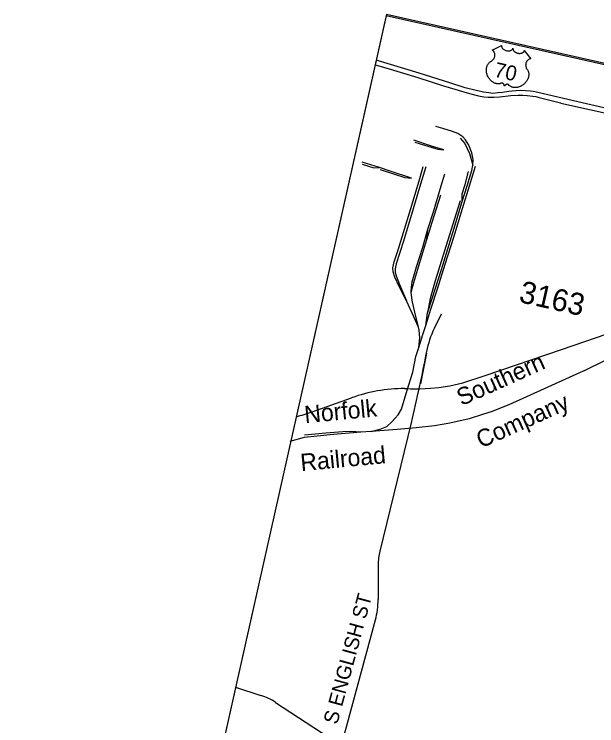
# Model space of a CAD drawing. Extents: x 1784499 to 1786147, y 841097 to 842538.
# Drawn here: x 1784498.9 to 1784675.3, y 842322.5 to 842538 of the extents above; entities that cross this region are included whole.
import ezdxf

# ---------------------------------------------------------------- set-up
doc = ezdxf.new("R2010")
doc.units = 0
for name, color, linetype in [('Exist Railroad Mainline', 7, 'Continuous'), ('Exist Railroad Mainline Label', 7, 'Continuous'), ('Exist Railroad Siding', 7, 'Continuous'), ('Exist Road Primary US Divided Attributed', 7, 'Continuous'), ('Exist Road Primary US Shield CELL', 7, 'Continuous'), ('Exist Road Primary US Shield Number Label', 7, 'Continuous'), ('Exist Road Secondary Type 51 Attributed', 7, 'Continuous'), ('Exist Road Secondary Type 51 Number Label', 7, 'Continuous'), ('Old_Level_40', 7, 'Continuous'), ('Prop DSN Text', 7, 'Continuous'), ('Scratch_Level_3', 7, 'Continuous')]:
    doc.layers.add(name, color=color, linetype=linetype)

msp = doc.modelspace()

# ---------------------------------------------------------------- linework, layer by layer
at = {"layer": 'Exist Railroad Mainline'}
msp.add_line((1784607.02, 842411.57), (1784603.83, 842411.38), dxfattribs=at)
for points in [[(1784691.01, 842439.02), (1784685.09, 842436.5), (1784677.01, 842432.69), (1784672.29, 842430.37), (1784671.48, 842430.01)], [(1784672.29, 842430.37), (1784648.63, 842419.69), (1784643.34, 842417.61), (1784641.02, 842416.82), (1784636.61, 842415.42)], [(1784636.61, 842415.42), (1784630.85, 842414.14), (1784626.2, 842413.36), (1784620.58, 842412.7), (1784614.83, 842412.18), (1784607.02, 842411.57)], [(1784603.83, 842411.38), (1784595.59, 842410.67), (1784586.73, 842409.78), (1784582.4, 842408.54)]]:
    msp.add_lwpolyline(points, dxfattribs=at)
at = {"layer": 'Exist Railroad Siding'}
for p, q in [((1784609.48, 842491.52), (1784604.3, 842493.15)), ((1784623.89, 842469.79), (1784624.18, 842472.9)), ((1784623.54, 842443.74), (1784624.03, 842447.53))]:
    msp.add_line(p, q, dxfattribs=at)
for points in [[(1784637.76, 842492.23), (1784637.87, 842493.96), (1784637.45, 842496.05), (1784636.51, 842498.36), (1784635.59, 842499.91), (1784634.7, 842500.82), (1784633.85, 842501.44), (1784633.19, 842501.88), (1784631.65, 842502.42), (1784628.73, 842503.34), (1784626.55, 842503.98)], [(1784628.98, 842496.93), (1784625.3, 842498.07), (1784619.9, 842499.79)], [(1784620.2, 842499.24), (1784624.1, 842498.02), (1784627.16, 842497.07), (1784628.98, 842496.93)], [(1784633.94, 842500.42), (1784635.3, 842498.87), (1784636.78, 842495.83), (1784637.76, 842492.23)], [(1784604.26, 842492.59), (1784607.76, 842491.49), (1784609.48, 842491.52)], [(1784634.51, 842481.24), (1784636.08, 842485.97), (1784637.44, 842490.65), (1784637.76, 842492.23)], [(1784619.15, 842488.35), (1784612.69, 842490.41), (1784609.48, 842491.52)], [(1784609.68, 842490.91), (1784613.7, 842489.65), (1784617.19, 842488.51), (1784619.15, 842488.35)], [(1784617.66, 842451.23), (1784615.43, 842455.54), (1784614.17, 842458.35), (1784613.6, 842459.95), (1784613.51, 842461.21), (1784613.95, 842462.96), (1784615.25, 842466.93), (1784617.06, 842472.93), (1784619.42, 842480.5), (1784621.73, 842488.23), (1784622.76, 842491.84)], [(1784623.49, 842491.72), (1784621.96, 842486.52), (1784619.66, 842479.02), (1784616.73, 842469.25), (1784614.59, 842462.43), (1784614.23, 842460.85), (1784614.2, 842459.9), (1784614.52, 842458.79), (1784615.6, 842456.12), (1784617.66, 842451.23)], [(1784623.54, 842443.74), (1784625.1, 842448.7), (1784627.02, 842454.77), (1784629.37, 842462.24), (1784631.98, 842470.48), (1784634.65, 842479.17), (1784636.75, 842486), (1784638.59, 842491.94)], [(1784634.51, 842481.24), (1784634.53, 842483.57), (1784635.47, 842486.44), (1784636.45, 842490.3)], [(1784624.18, 842472.9), (1784625.82, 842478.17), (1784628.16, 842486.04), (1784629.29, 842489.67)], [(1784623.89, 842469.79), (1784625.48, 842475.02), (1784628.04, 842483.26)], [(1784633.9, 842481.48), (1784632.13, 842475.68), (1784629.22, 842466.32), (1784626.4, 842457.23), (1784624.89, 842451.88), (1784624.03, 842447.53)], [(1784624.03, 842447.53), (1784625.49, 842451.84), (1784628.25, 842460.7), (1784631.68, 842471.87), (1784634.51, 842481.24)], [(1784619.12, 842453.83), (1784619.17, 842455.29), (1784619.36, 842456.92), (1784620.68, 842461.45), (1784622.58, 842467.43), (1784624.18, 842472.9)], [(1784619.12, 842453.83), (1784620.09, 842457.41), (1784622.32, 842464.82), (1784623.89, 842469.79)], [(1784621.27, 842443.18), (1784620.22, 842447.7), (1784619.43, 842451.24), (1784619.12, 842453.83)], [(1784621.27, 842443.18), (1784619.91, 842446.34), (1784617.75, 842450.96), (1784617.66, 842451.23)], [(1784621.46, 842437), (1784621.77, 842440.02), (1784621.54, 842442.3), (1784621.27, 842443.18)], [(1784621.46, 842437), (1784622.65, 842440.95), (1784623.54, 842443.74)], [(1784607.02, 842411.57), (1784609.68, 842412.32), (1784611.7, 842413.17), (1784613.24, 842414.52), (1784614.3, 842415.67), (1784615.2, 842416.67), (1784616.15, 842418.34), (1784617.91, 842424.08), (1784619.65, 842429.61), (1784620.55, 842434.31), (1784621.46, 842437)], [(1784603.83, 842411.38), (1784600.9, 842411.63), (1784598.45, 842411.52), (1784593.26, 842411.06), (1784586.82, 842410.5)]]:
    msp.add_lwpolyline(points, dxfattribs=at)
at = {"layer": 'Exist Road Primary US Divided Attributed'}
for points in [[(1784608.16, 842522.67), (1784611.39, 842521.75), (1784621.15, 842518.78), (1784628.84, 842516.34), (1784636.81, 842514), (1784639.45, 842513.24), (1784641.15, 842512.92), (1784642.37, 842512.84), (1784644.13, 842512.86), (1784645.93, 842512.95), (1784649.28, 842513.33), (1784651.55, 842513.49), (1784652.91, 842513.46), (1784654.24, 842513.4), (1784655.91, 842513.18), (1784656.81, 842513.03), (1784657.86, 842512.77), (1784664.37, 842511.11), (1784664.46, 842511.09), (1784673.09, 842509.12), (1784678.18, 842508.03)], [(1784685.73, 842507.7), (1784669.58, 842511.47), (1784657.44, 842514.28), (1784656.05, 842514.55), (1784655.12, 842514.68), (1784653.76, 842514.82), (1784652.09, 842514.83), (1784649.69, 842514.68), (1784648.71, 842514.58), (1784646.73, 842514.27), (1784645.3, 842514.14), (1784643.81, 842514.01), (1784642.65, 842514.13), (1784641.85, 842514.26), (1784641.03, 842514.38), (1784638.77, 842514.89), (1784635.46, 842515.72), (1784630.81, 842517.21), (1784621.54, 842520.1), (1784608.47, 842524.06)]]:
    msp.add_lwpolyline(points, dxfattribs=at)
at = {"layer": 'Exist Road Primary US Shield CELL'}
for p, q in [((1784646.49, 842528.48), (1784646.48, 842528.38)), ((1784649.89, 842527.59), (1784649.93, 842527.72)), ((1784649.93, 842527.72), (1784649.91, 842527.61)), ((1784653.34, 842526.88), (1784653.36, 842526.95))]:
    msp.add_line(p, q, dxfattribs=at)
at = {"layer": 'Exist Road Primary US Shield Number Label'}
for p, q in [((1784643.66, 842527.11), (1784646.49, 842528.48)), ((1784643.73, 842527.06), (1784643.66, 842527.11)), ((1784643.83, 842526.98), (1784643.73, 842527.06)), ((1784643.94, 842526.88), (1784643.83, 842526.98)), ((1784644.02, 842526.79), (1784643.94, 842526.88)), ((1784644.11, 842526.68), (1784644.02, 842526.79)), ((1784644.19, 842526.55), (1784644.11, 842526.68)), ((1784644.27, 842526.41), (1784644.19, 842526.55)), ((1784646.48, 842528.38), (1784646.47, 842528.26)), ((1784646.47, 842528.26), (1784646.48, 842528.19)), ((1784646.48, 842528.19), (1784646.51, 842528.07)), ((1784646.51, 842528.07), (1784646.57, 842527.91)), ((1784646.57, 842527.91), (1784646.66, 842527.75)), ((1784646.66, 842527.75), (1784646.78, 842527.6)), ((1784646.78, 842527.6), (1784646.86, 842527.51)), ((1784646.86, 842527.51), (1784647.01, 842527.39)), ((1784647.01, 842527.39), (1784647.17, 842527.27)), ((1784647.17, 842527.27), (1784647.37, 842527.16)), ((1784647.37, 842527.16), (1784647.57, 842527.07)), ((1784647.57, 842527.07), (1784647.8, 842526.99)), ((1784647.8, 842526.99), (1784648.02, 842526.94)), ((1784648.02, 842526.94), (1784648.27, 842526.9)), ((1784648.27, 842526.9), (1784648.56, 842526.89)), ((1784648.56, 842526.89), (1784648.69, 842526.9)), ((1784648.69, 842526.9), (1784648.84, 842526.91)), ((1784648.84, 842526.91), (1784648.98, 842526.94)), ((1784648.98, 842526.94), (1784649.14, 842526.98)), ((1784649.14, 842526.98), (1784649.28, 842527.03)), ((1784649.28, 842527.03), (1784649.38, 842527.08)), ((1784649.38, 842527.08), (1784649.54, 842527.17)), ((1784649.54, 842527.17), (1784649.67, 842527.27)), ((1784649.67, 842527.27), (1784649.72, 842527.33)), ((1784649.72, 842527.33), (1784649.78, 842527.39)), ((1784649.78, 842527.39), (1784649.86, 842527.53)), ((1784649.86, 842527.53), (1784649.89, 842527.59)), ((1784649.91, 842527.61), (1784649.91, 842527.53)), ((1784649.91, 842527.53), (1784649.91, 842527.46)), ((1784649.91, 842527.46), (1784649.92, 842527.38)), ((1784649.92, 842527.38), (1784649.95, 842527.27)), ((1784649.95, 842527.27), (1784649.99, 842527.17)), ((1784649.99, 842527.17), (1784650.07, 842527.02)), ((1784650.07, 842527.02), (1784650.12, 842526.94)), ((1784650.12, 842526.94), (1784650.17, 842526.88)), ((1784650.17, 842526.88), (1784650.31, 842526.73)), ((1784650.31, 842526.73), (1784650.47, 842526.59)), ((1784650.47, 842526.59), (1784650.56, 842526.53)), ((1784650.56, 842526.53), (1784650.65, 842526.47)), ((1784653.07, 842526.48), (1784653.15, 842526.55)), ((1784653.15, 842526.55), (1784653.21, 842526.63)), ((1784653.21, 842526.63), (1784653.27, 842526.71)), ((1784653.27, 842526.71), (1784653.31, 842526.8)), ((1784653.31, 842526.8), (1784653.34, 842526.88)), ((1784653.36, 842526.95), (1784655.33, 842524.5)), ((1784643.93, 842524.22), (1784644.03, 842524.34)), ((1784644.03, 842524.34), (1784644.1, 842524.44)), ((1784644.1, 842524.44), (1784644.19, 842524.59)), ((1784644.19, 842524.59), (1784644.25, 842524.69)), ((1784644.25, 842524.69), (1784644.31, 842524.83)), ((1784644.34, 842526.24), (1784644.27, 842526.41)), ((1784644.31, 842524.83), (1784644.36, 842524.97)), ((1784644.39, 842526.06), (1784644.34, 842526.24)), ((1784644.36, 842524.97), (1784644.4, 842525.14)), ((1784644.42, 842525.94), (1784644.39, 842526.06)), ((1784644.4, 842525.14), (1784644.43, 842525.28)), ((1784644.45, 842525.76), (1784644.42, 842525.94)), ((1784644.43, 842525.28), (1784644.45, 842525.45)), ((1784644.45, 842525.62), (1784644.45, 842525.76)), ((1784644.45, 842525.45), (1784644.45, 842525.62)), ((1784650.65, 842526.47), (1784650.76, 842526.41)), ((1784650.76, 842526.41), (1784650.88, 842526.35)), ((1784650.88, 842526.35), (1784651, 842526.3)), ((1784651, 842526.3), (1784651.12, 842526.26)), ((1784651.12, 842526.26), (1784651.25, 842526.22)), ((1784651.25, 842526.22), (1784651.36, 842526.19)), ((1784651.36, 842526.19), (1784651.49, 842526.16)), ((1784651.49, 842526.16), (1784651.61, 842526.14)), ((1784651.61, 842526.14), (1784651.74, 842526.13)), ((1784651.74, 842526.13), (1784651.88, 842526.12)), ((1784651.88, 842526.12), (1784651.99, 842526.12)), ((1784651.99, 842526.12), (1784652.15, 842526.13)), ((1784652.15, 842526.13), (1784652.29, 842526.14)), ((1784652.29, 842526.14), (1784652.41, 842526.17)), ((1784652.41, 842526.17), (1784652.58, 842526.21)), ((1784652.58, 842526.21), (1784652.72, 842526.26)), ((1784652.72, 842526.26), (1784652.82, 842526.31)), ((1784652.82, 842526.31), (1784652.95, 842526.38)), ((1784652.95, 842526.38), (1784653.07, 842526.48)), ((1784655.01, 842524.42), (1784654.82, 842524.34)), ((1784655.13, 842524.46), (1784655.01, 842524.42)), ((1784655.27, 842524.49), (1784655.13, 842524.46)), ((1784655.33, 842524.5), (1784655.27, 842524.49)), ((1784642.01, 842522.09), (1784642.07, 842522.27)), ((1784642.07, 842522.27), (1784642.14, 842522.47)), ((1784642.14, 842522.47), (1784642.22, 842522.63)), ((1784642.22, 842522.63), (1784642.28, 842522.75)), ((1784642.28, 842522.75), (1784642.37, 842522.88)), ((1784642.37, 842522.88), (1784642.47, 842523.04)), ((1784642.47, 842523.04), (1784642.59, 842523.18)), ((1784642.59, 842523.18), (1784642.69, 842523.29)), ((1784642.69, 842523.29), (1784642.82, 842523.41)), ((1784642.82, 842523.41), (1784642.94, 842523.51)), ((1784642.94, 842523.51), (1784643.09, 842523.62)), ((1784643.09, 842523.62), (1784643.25, 842523.71)), ((1784643.25, 842523.71), (1784643.39, 842523.78)), ((1784643.39, 842523.78), (1784643.56, 842523.88)), ((1784643.56, 842523.88), (1784643.65, 842523.95)), ((1784643.65, 842523.95), (1784643.76, 842524.05)), ((1784643.76, 842524.05), (1784643.85, 842524.14)), ((1784643.85, 842524.14), (1784643.93, 842524.22)), ((1784653.78, 842522.67), (1784653.77, 842522.58)), ((1784653.77, 842522.58), (1784653.78, 842522.45)), ((1784653.8, 842522.89), (1784653.78, 842522.78)), ((1784653.78, 842522.78), (1784653.78, 842522.67)), ((1784653.78, 842522.45), (1784653.79, 842522.31)), ((1784653.79, 842522.31), (1784653.81, 842522.17)), ((1784653.81, 842523), (1784653.8, 842522.89)), ((1784653.84, 842523.1), (1784653.81, 842523)), ((1784653.87, 842523.2), (1784653.84, 842523.1)), ((1784653.94, 842523.4), (1784653.87, 842523.2)), ((1784653.99, 842523.5), (1784653.94, 842523.4)), ((1784654.05, 842523.62), (1784653.99, 842523.5)), ((1784654.17, 842523.79), (1784654.05, 842523.62)), ((1784654.23, 842523.88), (1784654.17, 842523.79)), ((1784654.32, 842523.97), (1784654.23, 842523.88)), ((1784654.4, 842524.05), (1784654.32, 842523.97)), ((1784654.49, 842524.13), (1784654.4, 842524.05)), ((1784654.57, 842524.19), (1784654.49, 842524.13)), ((1784654.65, 842524.24), (1784654.57, 842524.19)), ((1784654.73, 842524.29), (1784654.65, 842524.24)), ((1784654.82, 842524.34), (1784654.73, 842524.29)), ((1784641.87, 842521.31), (1784641.89, 842521.52)), ((1784641.87, 842521.16), (1784641.87, 842521.31)), ((1784641.87, 842520.95), (1784641.87, 842521.16)), ((1784641.87, 842520.82), (1784641.87, 842520.95)), ((1784641.89, 842520.62), (1784641.87, 842520.82)), ((1784641.89, 842521.52), (1784641.92, 842521.73)), ((1784641.92, 842520.41), (1784641.89, 842520.62)), ((1784641.92, 842521.73), (1784641.97, 842521.93)), ((1784641.96, 842520.18), (1784641.92, 842520.41)), ((1784642, 842520.02), (1784641.96, 842520.18)), ((1784641.97, 842521.93), (1784642.01, 842522.09)), ((1784653.81, 842522.17), (1784653.88, 842521.94)), ((1784653.88, 842521.94), (1784653.97, 842521.69)), ((1784653.97, 842521.69), (1784654.04, 842521.55)), ((1784654.04, 842521.55), (1784654.12, 842521.43)), ((1784654.12, 842521.43), (1784654.24, 842521.27)), ((1784654.24, 842521.27), (1784654.3, 842521.18)), ((1784654.3, 842521.18), (1784654.38, 842521.07)), ((1784654.38, 842521.07), (1784654.49, 842520.86)), ((1784654.49, 842520.86), (1784654.53, 842520.76)), ((1784654.53, 842520.76), (1784654.57, 842520.66)), ((1784654.57, 842520.66), (1784654.61, 842520.55)), ((1784654.61, 842520.55), (1784654.64, 842520.43)), ((1784654.64, 842520.43), (1784654.67, 842520.34)), ((1784654.67, 842520.34), (1784654.7, 842520.11)), ((1784654.7, 842520.11), (1784654.72, 842519.9)), ((1784642.08, 842519.76), (1784642, 842520.02)), ((1784642.13, 842519.59), (1784642.08, 842519.76)), ((1784642.22, 842519.37), (1784642.13, 842519.59)), ((1784642.37, 842519.05), (1784642.22, 842519.37)), ((1784642.47, 842518.86), (1784642.37, 842519.05)), ((1784642.65, 842518.58), (1784642.47, 842518.86)), ((1784642.77, 842518.41), (1784642.65, 842518.58)), ((1784642.94, 842518.19), (1784642.77, 842518.41)), ((1784643.18, 842517.93), (1784642.94, 842518.19)), ((1784643.39, 842517.74), (1784643.18, 842517.93)), ((1784654.22, 842517.98), (1784654.12, 842517.81)), ((1784654.33, 842518.18), (1784654.22, 842517.98)), ((1784654.41, 842518.35), (1784654.33, 842518.18)), ((1784654.53, 842518.65), (1784654.41, 842518.35)), ((1784654.61, 842518.91), (1784654.53, 842518.65)), ((1784654.67, 842519.19), (1784654.61, 842518.91)), ((1784654.71, 842519.42), (1784654.67, 842519.19)), ((1784654.72, 842519.54), (1784654.71, 842519.42)), ((1784654.72, 842519.9), (1784654.73, 842519.79)), ((1784654.73, 842519.79), (1784654.72, 842519.54)), ((1784643.52, 842517.63), (1784643.39, 842517.74)), ((1784643.72, 842517.48), (1784643.52, 842517.63)), ((1784643.88, 842517.38), (1784643.72, 842517.48)), ((1784644.03, 842517.29), (1784643.88, 842517.38)), ((1784644.18, 842517.21), (1784644.03, 842517.29)), ((1784644.32, 842517.14), (1784644.18, 842517.21)), ((1784644.5, 842517.07), (1784644.32, 842517.14)), ((1784644.64, 842517.03), (1784644.5, 842517.07)), ((1784644.77, 842516.99), (1784644.64, 842517.03)), ((1784644.9, 842516.96), (1784644.77, 842516.99)), ((1784645.03, 842516.93), (1784644.9, 842516.96)), ((1784645.18, 842516.92), (1784645.03, 842516.93)), ((1784645.31, 842516.91), (1784645.18, 842516.92)), ((1784645.47, 842516.9), (1784645.31, 842516.91)), ((1784645.63, 842516.91), (1784645.47, 842516.9)), ((1784645.77, 842516.92), (1784645.63, 842516.91)), ((1784645.9, 842516.94), (1784645.77, 842516.92)), ((1784646.01, 842516.97), (1784645.9, 842516.94)), ((1784646.16, 842517.01), (1784646.01, 842516.97)), ((1784646.29, 842517.05), (1784646.16, 842517.01)), ((1784646.4, 842517.1), (1784646.29, 842517.05)), ((1784646.53, 842517.15), (1784646.4, 842517.1)), ((1784646.61, 842517.15), (1784646.53, 842517.15)), ((1784646.67, 842517.14), (1784646.61, 842517.15)), ((1784646.74, 842517.12), (1784646.67, 842517.14)), ((1784646.82, 842517.08), (1784646.74, 842517.12)), ((1784646.89, 842517.04), (1784646.82, 842517.08)), ((1784646.96, 842516.98), (1784646.89, 842517.04)), ((1784647.04, 842516.9), (1784646.96, 842516.98)), ((1784647.11, 842516.81), (1784647.04, 842516.9)), ((1784647.17, 842516.72), (1784647.11, 842516.81)), ((1784647.24, 842516.6), (1784647.17, 842516.72)), ((1784647.27, 842516.51), (1784647.24, 842516.6)), ((1784647.3, 842516.42), (1784647.27, 842516.51)), ((1784647.33, 842516.31), (1784647.3, 842516.42)), ((1784647.33, 842516.15), (1784647.33, 842516.31)), ((1784647.38, 842516.26), (1784647.33, 842516.15)), ((1784647.43, 842516.34), (1784647.38, 842516.26)), ((1784647.48, 842516.39), (1784647.43, 842516.34)), ((1784647.59, 842516.5), (1784647.48, 842516.39)), ((1784647.64, 842516.55), (1784647.59, 842516.5)), ((1784647.72, 842516.6), (1784647.64, 842516.55)), ((1784647.82, 842516.66), (1784647.72, 842516.6)), ((1784647.9, 842516.7), (1784647.82, 842516.66)), ((1784648, 842516.74), (1784647.9, 842516.7)), ((1784648.07, 842516.76), (1784648, 842516.74)), ((1784648.19, 842516.77), (1784648.07, 842516.76)), ((1784648.3, 842516.77), (1784648.19, 842516.77)), ((1784648.42, 842516.74), (1784648.3, 842516.77)), ((1784648.46, 842516.72), (1784648.42, 842516.74)), ((1784648.54, 842516.65), (1784648.46, 842516.72)), ((1784648.79, 842516.4), (1784648.54, 842516.65)), ((1784648.95, 842516.27), (1784648.79, 842516.4)), ((1784649.11, 842516.17), (1784648.95, 842516.27)), ((1784649.29, 842516.07), (1784649.11, 842516.17)), ((1784649.46, 842515.99), (1784649.29, 842516.07)), ((1784649.63, 842515.92), (1784649.46, 842515.99)), ((1784649.81, 842515.87), (1784649.63, 842515.92)), ((1784650, 842515.83), (1784649.81, 842515.87)), ((1784650.14, 842515.8), (1784650, 842515.83)), ((1784650.29, 842515.78), (1784650.14, 842515.8)), ((1784650.45, 842515.77), (1784650.29, 842515.78)), ((1784650.58, 842515.77), (1784650.45, 842515.77)), ((1784650.96, 842515.79), (1784650.58, 842515.77)), ((1784651.19, 842515.82), (1784650.96, 842515.79)), ((1784651.37, 842515.86), (1784651.19, 842515.82)), ((1784651.58, 842515.91), (1784651.37, 842515.86)), ((1784651.82, 842515.99), (1784651.58, 842515.91)), ((1784652.08, 842516.09), (1784651.82, 842515.99)), ((1784652.27, 842516.17), (1784652.08, 842516.09)), ((1784652.4, 842516.24), (1784652.27, 842516.17)), ((1784652.62, 842516.36), (1784652.4, 842516.24)), ((1784652.8, 842516.48), (1784652.62, 842516.36)), ((1784653.02, 842516.63), (1784652.8, 842516.48)), ((1784653.21, 842516.78), (1784653.02, 842516.63)), ((1784653.37, 842516.93), (1784653.21, 842516.78)), ((1784653.51, 842517.05), (1784653.37, 842516.93)), ((1784653.63, 842517.18), (1784653.51, 842517.05)), ((1784653.81, 842517.38), (1784653.63, 842517.18)), ((1784653.95, 842517.56), (1784653.81, 842517.38)), ((1784654.12, 842517.81), (1784653.95, 842517.56))]:
    msp.add_line(p, q, dxfattribs=at)
at = {"layer": 'Exist Road Secondary Type 51 Attributed'}
for p, q in [((1784628.2, 842447.1), (1784626.1, 842442.81)), ((1784623.69, 842435.35), (1784621.97, 842426.05)), ((1784589.14, 842417.57), (1784601.06, 842421.82)), ((1784619.14, 842414.28), (1784609.58, 842375.33)), ((1784609.09, 842371.24), (1784609.08, 842360.73)), ((1784592.03, 842294.86), (1784608.26, 842354.55)), ((1784565.88, 842334.16), (1784573.61, 842331.68)), ((1784578, 842329.58), (1784594.23, 842318.89))]:
    msp.add_line(p, q, dxfattribs=at)
msp.add_lwpolyline([(1784617.08, 842424.61), (1784618.07, 842424.61), (1784618.92, 842424.58), (1784621.69, 842424.52), (1784624.93, 842424.73), (1784627.44, 842424.97), (1784630.85, 842425.46), (1784634.75, 842426.39), (1784641.54, 842428.56), (1784664.63, 842436.41), (1784681.73, 842442.31)], dxfattribs=at)
for centre, radius, start, end in [((1784650.33, 842430.9), 27.01, 153.8208, 169.5253), ((1784247.48, 842505.5), 382.7, 346.21, 349.5253), ((1784617.19, 842376.53), 48.08, 90.1386, 109.6101), ((1784570.23, 842470.65), 56.34, 284.4176, 289.6101), ((1784626.3, 842371.23), 17.21, 166.21, 179.9741), ((1784585.51, 842360.74), 23.57, 344.7891, 359.9741), ((1784568.15, 842314.64), 17.9, 56.6238, 72.2302)]:
    msp.add_arc(centre, radius, start, end, dxfattribs=at)
at = {"layer": 'Old_Level_40'}
for q in [(1784498.88, 842035.39), (1785099.64, 842428.53)]:
    msp.add_line((1784611.59, 842537.98), q, dxfattribs=at)
at = {"layer": 'Scratch_Level_3'}
msp.add_lwpolyline([(1785039.41, 842390.83), (1785050.23, 842439.1), (1784611.48, 842537.49), (1784510.23, 842085.98), (1784998.27, 841976.54), (1785088.7, 842379.78)], close=True, dxfattribs=at)

# ---------------------------------------------------------------- texts
at = {"layer": 'Exist Railroad Mainline Label'}
for s, rotation, p in [('Southern', 24.2119, (1784634.34, 842419.26)), ('Norfolk', 5.3977, (1784586.98, 842414.12)), ('Company', 24.2119, (1784640.26, 842406.45)), ('Railroad', 5.3977, (1784585.79, 842399.6))]:
    msp.add_text(s, height=5.207, rotation=rotation, dxfattribs=at).set_placement(p)
at = {"layer": 'Exist Road Primary US Shield Number Label'}
msp.add_text('70', height=4.513, rotation=347.3599, dxfattribs=at).set_placement((1784643.98, 842519.11))
at = {"layer": 'Exist Road Secondary Type 51 Number Label'}
msp.add_text('3163', height=6.665, rotation=347.3599, dxfattribs=at).set_placement((1784651.44, 842450.86))
at = {"layer": 'Prop DSN Text'}
msp.add_text('S ENGLISH ST', height=4.3971, rotation=74.8477, dxfattribs=at).set_placement((1784596.69, 842322.68))

doc.saveas('drawing.dxf')
